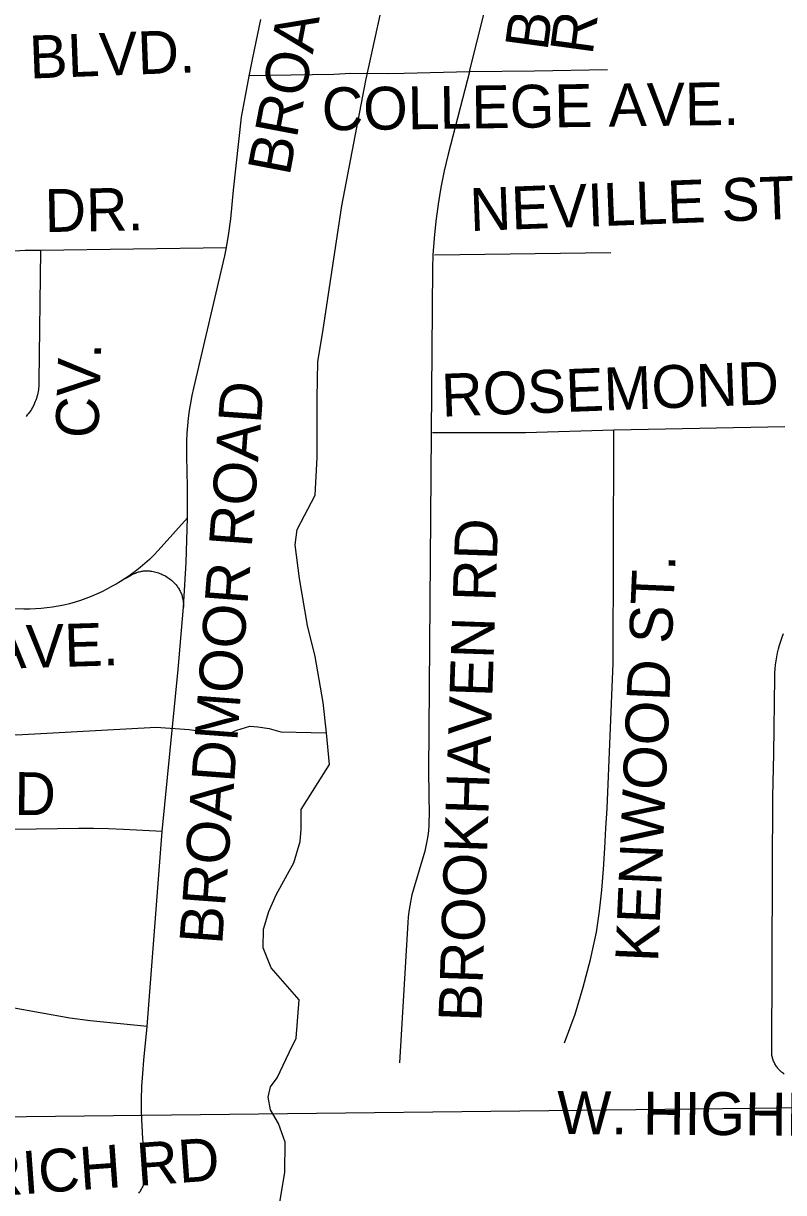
# Model space of a CAD drawing. Extents: x 1670563 to 1761545, y 515755 to 578944.
# Drawn here: x 1689813 to 1691143, y 543926 to 545971 of the extents above; entities that cross this region are included whole.
import ezdxf

# ---------------------------------------------------------------- set-up
doc = ezdxf.new("R2010")
doc.units = 0
for name, color, linetype in [('5_sectionlines', 7, 'Continuous'), ('SHP_LINE', 7, 'Continuous'), ('STREETCL', 7, 'Continuous'), ('STRNAMES', 7, 'Continuous')]:
    doc.layers.add(name, color=color, linetype=linetype)

msp = doc.modelspace()

# ---------------------------------------------------------------- linework, layer by layer
at = {"layer": '5_sectionlines'}
msp.add_lwpolyline([(1685823.9, 543970.2), (1688486.3, 544044.1), (1693687.1, 544103.2), (1698961.5, 544118.1), (1704285.9, 544155), (1709574.3, 544171.9), (1714958.5, 544246.7), (1716656.1, 544265.6)], dxfattribs=at)
at = {"layer": 'SHP_LINE'}
for points in [[(1690343, 544730), (1690337, 544783), (1690323, 544864), (1690310, 544918), (1690296, 545000), (1690288, 545059), (1690292, 545086), (1690323, 545146), (1690327, 545212), (1690327, 545316), (1690328, 545379), (1690337, 545436), (1690370, 545652), (1690412, 545871), (1690438, 545991)], [(1688220, 544697), (1688259, 544706), (1688317, 544700), (1688390, 544699), (1688549, 544712), (1688685, 544712), (1688786, 544709), (1688945, 544730), (1689156, 544725), (1689369, 544717), (1689544, 544740), (1689801, 544727), (1690045, 544740), (1690103, 544736), (1690153, 544729), (1690173, 544729), (1690186, 544735), (1690209, 544742), (1690223, 544741), (1690243, 544738), (1690263, 544732), (1690343, 544730)], [(1690234, 543744), (1690270, 543962), (1690271, 544014), (1690259, 544047), (1690245, 544071), (1690241, 544093), (1690245, 544111), (1690257, 544127), (1690278, 544171), (1690290, 544196), (1690295, 544263), (1690246, 544319), (1690232, 544354), (1690233, 544387), (1690242, 544418), (1690255, 544447), (1690275, 544483), (1690286, 544503), (1690297, 544540), (1690299, 544562), (1690299, 544596), (1690348, 544675), (1690343, 544730)]]:
    msp.add_lwpolyline(points, dxfattribs=at)
at = {"layer": 'STREETCL'}
for points in [[(1690593, 545886.2), (1690632.6, 546046.1), (1690660, 546174.6), (1690663.9, 546200.4), (1690667.1, 546226.4), (1690669.4, 546252.4), (1690670.9, 546278.5), (1690671.7, 546304.6), (1690671.6, 546330.8), (1690673.2, 546482.5), (1690673.3, 546498), (1690673.8, 546513.4), (1690674.9, 546528.8), (1690676.4, 546544.2), (1690678.4, 546559.5), (1690680.9, 546574.7), (1690683.9, 546589.9), (1690687.4, 546604.9), (1690691.3, 546619.9), (1690726.1, 546724.4)], [(1690207.5, 545879.1), (1690214, 545911), (1690228.1, 545977.7)], [(1690167.9, 545579.2), (1690172.1, 545604.2), (1690175.6, 545629.2), (1690178.3, 545654.4), (1690180.3, 545679.6), (1690194.4, 545807.1), (1690207.5, 545879.1)], [(1690593, 545886.2), (1690479.1, 545883.3), (1690451.5, 545882.7), (1690385.8, 545883.3), (1690355.7, 545881.5), (1690206.4, 545879.3)], [(1690593, 545886.2), (1690555.9, 545742.5), (1690549, 545713.5), (1690543.1, 545684.2), (1690538.2, 545654.8), (1690534.2, 545625.3), (1690531.3, 545595.6), (1690529.3, 545565.8)], [(1690834.7, 545890.2), (1690706.9, 545887.7), (1690593, 545886.2)], [(1689377, 545349.6), (1689677.9, 545532.4), (1689685.7, 545537.2), (1689693.6, 545541.7), (1689701.6, 545546), (1689709.8, 545550), (1689718.2, 545553.6), (1689726.6, 545557), (1689735.2, 545560.2), (1689743.9, 545563), (1689752.7, 545565.5), (1689761.5, 545567.7), (1689770.4, 545569.6), (1689779.4, 545571.1), (1689788.5, 545572.4), (1689797.5, 545573.4), (1689806.6, 545574), (1689815.7, 545574.3), (1689824.9, 545574.4), (1689842.9, 545574.6)], [(1689842.9, 545574), (1689840, 545345.3), (1689840.1, 545342.3), (1689840, 545339.2), (1689839.8, 545336.2), (1689839.5, 545333.2), (1689839.2, 545330.1), (1689838.7, 545327.1), (1689838.1, 545324.1), (1689837.4, 545321.2), (1689836.6, 545318.2), (1689835.7, 545315.3), (1689834.7, 545312.4), (1689833.6, 545309.6), (1689832.4, 545306.8), (1689831.1, 545304), (1689829.7, 545301.3), (1689828.3, 545298.6), (1689826.7, 545296), (1689825, 545293.5), (1689823.3, 545291), (1689821.4, 545288.5), (1689819.5, 545286.2), (1689817.5, 545283.8)], [(1689842.9, 545574.6), (1690167.9, 545579.2)], [(1690100.1, 545106.3), (1690100.1, 545160.3), (1690098.9, 545214.4), (1690098.6, 545227.7), (1690098.7, 545241), (1690099.2, 545254.3), (1690100.2, 545267.5), (1690101.5, 545280.8), (1690103.3, 545293.9), (1690105.5, 545307), (1690108.1, 545320.1), (1690111.1, 545333), (1690165, 545564.6), (1690167.9, 545579.2)], [(1690529.3, 545565.8), (1690528.4, 545543.5), (1690526.1, 545255.1)], [(1690840.3, 545569.6), (1690531.9, 545565.7)], [(1690845.8, 545259.4), (1690691.1, 545255.1), (1690528.5, 545255.1)], [(1690759.5, 544188), (1690778.2, 544238.2), (1690792.3, 544285.6), (1690804.8, 544333.5), (1690815.5, 544381.7), (1690820.6, 544418.3), (1690824.7, 544454.9), (1690827.8, 544491.7), (1690829.9, 544528.5), (1690831.8, 544563.2), (1690834.3, 544597.9), (1690844.4, 544851.9), (1690845.8, 545241.6), (1690845.8, 545259.4)], [(1691145.1, 545265.2), (1690846.2, 545259.4), (1690845.8, 545259.4)], [(1690526.1, 545255.1), (1690521.3, 544662.1), (1690522.4, 544585.9), (1690522.3, 544576.9), (1690521.9, 544567.9), (1690521.2, 544558.9), (1690520.1, 544549.9), (1690518.7, 544541), (1690517.1, 544532.2), (1690515.1, 544523.4), (1690495, 544456.5), (1690492.6, 544447), (1690490.5, 544437.3), (1690488.7, 544427.6), (1690487.2, 544417.8), (1690486.1, 544408), (1690485.2, 544398.2), (1690484.7, 544388.3), (1690470.6, 544153.2)], [(1690100.1, 545106.3), (1690048.5, 545049), (1690041, 545041.2), (1690033.2, 545033.6), (1690025.1, 545026.3), (1690016.8, 545019.3), (1690008.3, 545012.6), (1689999.5, 545006.2), (1689990.6, 545000.1)], [(1690092.6, 544949.8), (1690097.7, 545028), (1690100.1, 545106.3)], [(1689990.6, 545000.1), (1690001.8, 545006.6), (1690003.5, 545007.5), (1690005.2, 545008.4), (1690007, 545009.1), (1690008.8, 545009.8), (1690010.6, 545010.5), (1690012.4, 545011.1), (1690014.2, 545011.6), (1690016.1, 545012.1), (1690018, 545012.5), (1690019.9, 545012.9), (1690021.8, 545013.1), (1690023.7, 545013.4), (1690025.6, 545013.5), (1690027.5, 545013.6), (1690029.4, 545013.6), (1690031.4, 545013.6), (1690033.3, 545013.5), (1690035.2, 545013.3), (1690037.6, 545013), (1690039.9, 545012.6), (1690042.2, 545012.1), (1690044.6, 545011.5), (1690046.9, 545010.8), (1690049.1, 545010.1), (1690051.4, 545009.2), (1690053.6, 545008.3), (1690055.8, 545007.4), (1690057.9, 545006.3), (1690060, 545005.2), (1690062.1, 545004), (1690064.1, 545002.7), (1690066.1, 545001.4), (1690068.1, 545000), (1690070, 544998.5), (1690071.8, 544997), (1690073.6, 544995.4), (1690075.3, 544993.8), (1690077, 544992), (1690078.6, 544990.3), (1690079.8, 544988.9), (1690081, 544987.5), (1690082.1, 544986), (1690083.1, 544984.5), (1690084.2, 544983), (1690085.1, 544981.4), (1690086, 544979.8), (1690086.9, 544978.2), (1690087.7, 544976.6), (1690088.4, 544974.9), (1690089.1, 544973.2), (1690089.7, 544971.5), (1690090.3, 544969.7), (1690090.8, 544968), (1690091.3, 544966.2), (1690091.7, 544964.4), (1690092, 544962.6), (1690092.3, 544960.8), (1690092.5, 544959), (1690092.6, 544957.1), (1690092.7, 544955.3), (1690092.7, 544953.5), (1690092.7, 544951.6), (1690092.6, 544949.8)], [(1689990.6, 545000.1), (1689982.8, 544995.2), (1689974.9, 544990.4), (1689966.9, 544986), (1689958.7, 544981.7), (1689949.8, 544977.1), (1689940.7, 544972.7), (1689931.5, 544968.7), (1689922.2, 544965), (1689912.7, 544961.6), (1689903.1, 544958.6), (1689893.5, 544955.9), (1689883.7, 544953.5), (1689873.8, 544951.5), (1689863.9, 544949.9), (1689854, 544948.6), (1689844, 544947.6), (1689833.9, 544947), (1689823.9, 544946.7), (1689813.8, 544946.8), (1689651.8, 544947.3), (1689526, 544945.5)], [(1690055.8, 544557.8), (1690083.5, 544841), (1690092.6, 544949.8)], [(1691143.8, 544133.2), (1691142.4, 544134.2), (1691141, 544135.3), (1691139.6, 544136.4), (1691138.3, 544137.5), (1691137, 544138.7), (1691135.7, 544140), (1691134.5, 544141.2), (1691133.4, 544142.6), (1691132.3, 544143.9), (1691131.2, 544145.3), (1691130.2, 544146.7), (1691129.2, 544148.2), (1691128.3, 544149.7), (1691127.5, 544151.2), (1691126.6, 544152.8), (1691125.9, 544154.4), (1691125.2, 544156), (1691124.6, 544157.6), (1691124, 544159.2), (1691123.4, 544160.9), (1691123, 544162.6), (1691122.6, 544164.3), (1691122.2, 544166), (1691122.8, 544331.1), (1691123.5, 544487.7), (1691124.1, 544618.1), (1691125.4, 544693.4), (1691127.3, 544827.6), (1691127.5, 544834.7), (1691128, 544841.9), (1691128.7, 544849), (1691129.6, 544856), (1691130.8, 544863), (1691132.2, 544870), (1691133.8, 544877), (1691135.7, 544883.8), (1691137.8, 544890.7), (1691140.2, 544897.4), (1691142.7, 544904)], [(1690055.8, 544557.8), (1689987.9, 544561.3), (1689961.8, 544562.6), (1689935.7, 544563.1), (1689909.6, 544563.1), (1688977.7, 544548.3), (1688973.1, 544548.2), (1688968.6, 544548), (1688964, 544547.6), (1688959.5, 544547.1), (1688955, 544546.4), (1688950.5, 544545.6), (1688946, 544544.6), (1688941.6, 544543.5), (1688937.2, 544542.2), (1688932.9, 544540.8), (1688928.6, 544539.2), (1688924.4, 544537.5), (1688920.2, 544535.7), (1688916.1, 544533.7), (1688912.1, 544531.6), (1688908.1, 544529.3), (1688904.2, 544526.9), (1688836.4, 544483.5)], [(1690029.1, 544216.4), (1690055.8, 544557.8)], [(1690029.1, 544216.4), (1689929.4, 544226.7), (1689893.9, 544230.9), (1689790.4, 544250)], [(1690014.8, 543925.1), (1690016.1, 543926.8), (1690017.4, 543928.6), (1690018.5, 543930.4), (1690019.7, 543932.3), (1690020.7, 543934.1), (1690021.7, 543936.1), (1690022.6, 543938), (1690023.5, 543940), (1690024.3, 543942.1), (1690025, 543944.1), (1690025.6, 543946.2), (1690026.2, 543948.3), (1690026.7, 543950.4), (1690027.1, 543952.5), (1690027.5, 543954.7), (1690027.7, 543956.8), (1690027.9, 543959), (1690028, 543961.1), (1690028.1, 543963.3), (1690028, 543965.5), (1690027.9, 543967.6), (1690027.8, 543969.8), (1690027.5, 543971.9), (1690027.2, 543974.1), (1690024.2, 543996.9), (1690021.9, 544019.8), (1690020.4, 544042.7), (1690019.6, 544065.7), (1690019.5, 544088.7), (1690020.2, 544111.6), (1690021.6, 544134.6), (1690023.7, 544157.5), (1690029.1, 544216.4)]]:
    msp.add_lwpolyline(points, dxfattribs=at)

# ---------------------------------------------------------------- texts
at = {"layer": 'STRNAMES'}
for s, rotation, p in [('BROOKHAVEN', 82.2597, (1690729.4, 545921.6)), ('BROADMOOR  RD.', 79.2114, (1690278.3, 545702.9)), (' RD.', 82.2597, (1690804.5, 545886.8)), ('BLVD.', 2.1804, (1689824.4, 545874.6)), ('COLLEGE AVE.', 0.7769, (1690335.2, 545783.8)), ('NEVILLE ST', 2.1804, (1690594.9, 545607.8)), ('DR.', 1.1044, (1689850.7, 545606)), (' CV.', 88.1165, (1689942.8, 545216.9)), ('ROSEMOND AVE.', 2.1804, (1690545.4, 545283.1)), ('BROADMOOR ROAD', 85.741, (1690160.4, 544358.6)), ('BROOKHAVEN RD', 88.0595, (1690613.8, 544224)), ('KENWOOD ST.', 87.5182, (1690923, 544328.4)), ('ROSEMOND AVE.', 1.7772, (1689133.6, 544822.3)), ('SHADY GROVE ROAD', 359.56, (1688816.1, 544594.1)), ('W. HIGHLAND DR', 359.5849, (1690746.3, 544028.7)), ('RICH RD', 4.1391, (1689741.3, 543918))]:
    msp.add_text(s, height=75, rotation=rotation, dxfattribs=at).set_placement(p)

doc.saveas('drawing.dxf')
